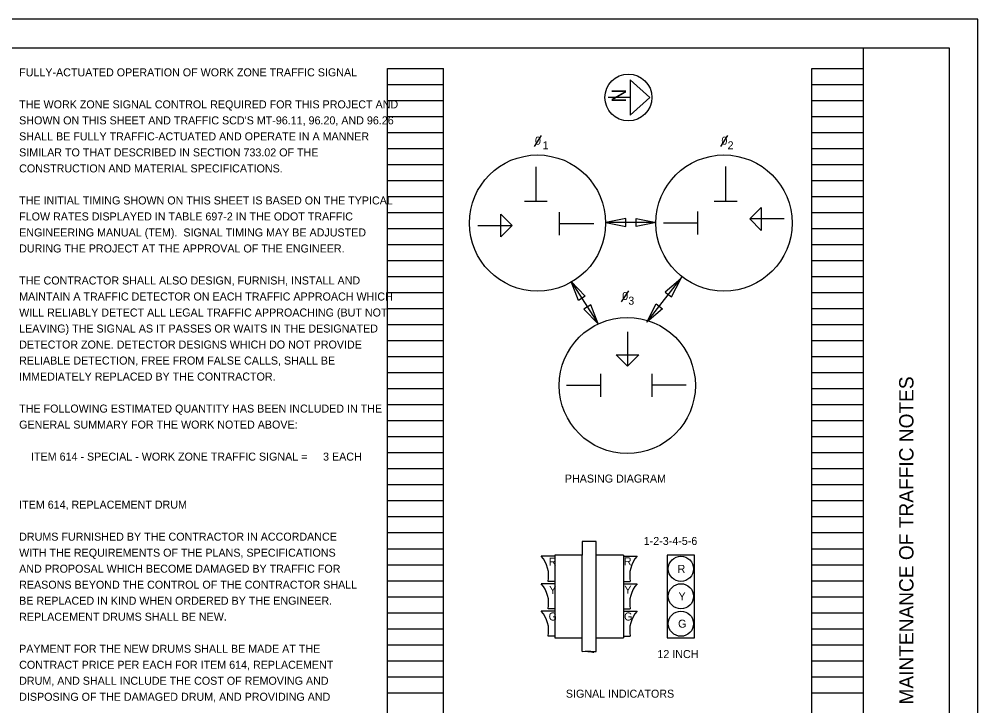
# Model space of a CAD drawing. Extents: x 0 to 34, y 0 to 22.
# Drawn here: x 17.24 to 34, y 9.99 to 22 of the extents above; entities that cross this region are included whole.
import ezdxf

# ---------------------------------------------------------------- set-up
doc = ezdxf.new("R2010")
doc.units = 0
for name, color, linetype in [('Default', 7, 'Continuous'), ('SG_P_Heads', 7, 'Continuous'), ('SH_Border', 7, 'Continuous'), ('SH_Cut_Line', 7, 'Continuous'), ('SH_Data', 7, 'Continuous'), ('SH_Masking', 7, 'Continuous'), ('SH_Text', 7, 'Continuous'), ('TX_P_1', 7, 'Continuous')]:
    doc.layers.add(name, color=color, linetype=linetype)

msp = doc.modelspace()

# ---------------------------------------------------------------- linework, layer by layer
at = {"layer": 'Default'}
for p, q in [((27.325, 12.863), (27.085, 12.863)), ((27.085, 12.863), (27.085, 12.624)), ((27.325, 10.942), (27.325, 12.863)), ((26.607, 12.607), (26.367, 12.607)), ((27.085, 12.624), (26.607, 12.624)), ((26.607, 12.624), (26.607, 11.182)), ((27.085, 11.182), (27.085, 12.624)), ((27.803, 12.624), (27.325, 12.624)), ((27.803, 12.624), (27.803, 11.182)), ((27.803, 12.607), (28.043, 12.607)), ((29.049, 12.624), (28.571, 12.624)), ((28.571, 12.624), (28.571, 11.182)), ((29.049, 11.182), (29.049, 12.624)), ((26.607, 12.127), (26.367, 12.127)), ((26.607, 12.167), (26.487, 12.167)), ((27.803, 12.167), (27.923, 12.167)), ((27.803, 12.127), (28.043, 12.127)), ((26.607, 11.648), (26.367, 11.648)), ((26.607, 11.687), (26.487, 11.687)), ((27.803, 11.687), (27.923, 11.687)), ((27.803, 11.648), (28.043, 11.648)), ((26.607, 11.208), (26.487, 11.208)), ((26.607, 11.182), (27.085, 11.182)), ((27.085, 10.942), (27.085, 11.182)), ((27.325, 11.182), (27.803, 11.182)), ((27.803, 11.208), (27.923, 11.208)), ((28.571, 11.182), (29.049, 11.182))]:
    msp.add_line(p, q, dxfattribs=at)
for centre in [(28.809, 12.387), (28.809, 11.907), (28.809, 11.428)]:
    msp.add_circle(centre, 0.22, dxfattribs=at)
for centre, start, end in [((25.992, 12.268), 348.4413, 42.0232), ((28.418, 12.268), 137.9768, 191.5587), ((25.992, 11.788), 348.4413, 42.0232), ((28.418, 11.788), 137.9768, 191.5587), ((25.992, 11.309), 348.4413, 42.0232), ((28.418, 11.309), 137.9768, 191.5587)]:
    msp.add_arc(centre, 0.505, start, end, dxfattribs=at)
msp.add_open_spline([(27.085, 10.942), (27.152, 10.961), (27.266, 10.92), (27.325, 10.942), (27.085, 10.942), (27.325, 10.942)], degree=3, dxfattribs=at)
at = {"layer": 'SG_P_Heads'}
for p, q in [((26.274, 19.417), (26.274, 18.816)), ((29.591, 19.421), (29.591, 18.82)), ((26.073, 18.816), (26.473, 18.816)), ((29.391, 18.82), (29.791, 18.82)), ((26.683, 18.624), (26.683, 18.224)), ((29.103, 18.237), (29.103, 18.637)), ((28.502, 18.437), (29.103, 18.437)), ((30.614, 18.507), (30.013, 18.507)), ((25.26, 18.392), (25.861, 18.392)), ((27.284, 18.423), (26.683, 18.423)), ((27.876, 16.53), (27.876, 15.929)), ((27.412, 15.397), (27.412, 15.797)), ((28.303, 15.797), (28.303, 15.397)), ((26.811, 15.597), (27.412, 15.597)), ((28.903, 15.597), (28.303, 15.597))]:
    msp.add_line(p, q, dxfattribs=at)
for points in [[(30.213, 18.307), (30.013, 18.507), (30.213, 18.707)], [(25.661, 18.592), (25.861, 18.392), (25.661, 18.192)], [(27.845, 18.513), (27.495, 18.443), (27.845, 18.373)], [(28.029, 18.513), (28.379, 18.443), (28.029, 18.373)], [(28.647, 17.142), (28.806, 17.461), (28.536, 17.228)], [(27.019, 17.078), (26.892, 17.411), (27.138, 17.153)], [(27.114, 16.928), (27.36, 16.67), (27.232, 17.003)], [(28.486, 16.935), (28.216, 16.701), (28.375, 17.02)], [(28.076, 16.129), (27.876, 15.929), (27.676, 16.129)]]:
    msp.add_lwpolyline(points, close=True, dxfattribs=at)
at = {"layer": 'SH_Border'}
msp.add_line((32, 0.5), (32, 21.5), dxfattribs=at)
msp.add_lwpolyline([(1.5, 21.5), (33.5, 21.5), (33.5, 0.5), (1.5, 0.5)], close=True, dxfattribs=at)
at = {"layer": 'SH_Cut_Line'}
msp.add_lwpolyline([(0, 0), (34, 0), (34, 22), (0, 22)], close=True, dxfattribs=at)
at = {"layer": 'SH_Data'}
for p, q in [((23.68, 0.98), (23.68, 21.14)), ((23.68, 21.14), (24.66, 21.14)), ((24.66, 0.98), (24.66, 21.14)), ((31.1, 0.98), (31.1, 21.14)), ((31.1, 21.14), (32, 21.14)), ((32, 0.98), (32, 21.14)), ((23.68, 20.86), (24.66, 20.86)), ((31.1, 20.86), (32, 20.86)), ((23.68, 20.58), (24.66, 20.58)), ((31.1, 20.58), (32, 20.58)), ((23.68, 20.3), (24.66, 20.3)), ((31.1, 20.3), (32, 20.3)), ((23.68, 20.02), (24.66, 20.02)), ((26.367, 19.968), (26.242, 19.775)), ((29.626, 19.968), (29.501, 19.775)), ((31.1, 20.02), (32, 20.02)), ((23.68, 19.74), (24.66, 19.74)), ((31.1, 19.74), (32, 19.74)), ((23.68, 19.46), (24.66, 19.46)), ((31.1, 19.46), (32, 19.46)), ((23.68, 19.18), (24.66, 19.18)), ((31.1, 19.18), (32, 19.18)), ((23.68, 18.9), (24.66, 18.9)), ((31.1, 18.9), (32, 18.9)), ((23.68, 18.62), (24.66, 18.62)), ((31.1, 18.62), (32, 18.62)), ((28.369, 18.443), (27.495, 18.443)), ((23.68, 18.34), (24.66, 18.34)), ((31.1, 18.34), (32, 18.34)), ((23.68, 18.06), (24.66, 18.06)), ((31.1, 18.06), (32, 18.06)), ((23.68, 17.78), (24.66, 17.78)), ((31.1, 17.78), (32, 17.78)), ((23.68, 17.5), (24.66, 17.5)), ((28.236, 16.728), (28.831, 17.494)), ((31.1, 17.5), (32, 17.5)), ((26.897, 17.402), (27.36, 16.67)), ((23.68, 17.22), (24.66, 17.22)), ((27.89, 17.251), (27.765, 17.059)), ((31.1, 17.22), (32, 17.22)), ((23.68, 16.94), (24.66, 16.94)), ((31.1, 16.94), (32, 16.94)), ((23.68, 16.66), (24.66, 16.66)), ((31.1, 16.66), (32, 16.66)), ((23.68, 16.38), (24.66, 16.38)), ((31.1, 16.38), (32, 16.38)), ((23.68, 16.1), (24.66, 16.1)), ((31.1, 16.1), (32, 16.1)), ((23.68, 15.82), (24.66, 15.82)), ((31.1, 15.82), (32, 15.82)), ((23.68, 15.54), (24.66, 15.54)), ((31.1, 15.54), (32, 15.54)), ((23.68, 15.26), (24.66, 15.26)), ((31.1, 15.26), (32, 15.26)), ((23.68, 14.98), (24.66, 14.98)), ((31.1, 14.98), (32, 14.98)), ((23.68, 14.7), (24.66, 14.7)), ((31.1, 14.7), (32, 14.7)), ((23.68, 14.42), (24.66, 14.42)), ((31.1, 14.42), (32, 14.42)), ((23.68, 14.14), (24.66, 14.14)), ((31.1, 14.14), (32, 14.14)), ((23.68, 13.86), (24.66, 13.86)), ((31.1, 13.86), (32, 13.86)), ((23.68, 13.58), (24.66, 13.58)), ((31.1, 13.58), (32, 13.58)), ((23.68, 13.3), (24.66, 13.3)), ((31.1, 13.3), (32, 13.3)), ((23.68, 13.02), (24.66, 13.02)), ((31.1, 13.02), (32, 13.02)), ((23.68, 12.74), (24.66, 12.74)), ((31.1, 12.74), (32, 12.74)), ((23.68, 12.46), (24.66, 12.46)), ((31.1, 12.46), (32, 12.46)), ((23.68, 12.18), (24.66, 12.18)), ((31.1, 12.18), (32, 12.18)), ((23.68, 11.9), (24.66, 11.9)), ((31.1, 11.9), (32, 11.9)), ((23.68, 11.62), (24.66, 11.62)), ((31.1, 11.62), (32, 11.62)), ((23.68, 11.34), (24.66, 11.34)), ((31.1, 11.34), (32, 11.34)), ((23.68, 11.06), (24.66, 11.06)), ((31.1, 11.06), (32, 11.06)), ((23.68, 10.78), (24.66, 10.78)), ((31.1, 10.78), (32, 10.78)), ((23.68, 10.5), (24.66, 10.5)), ((31.1, 10.5), (32, 10.5)), ((23.68, 10.22), (24.66, 10.22)), ((31.1, 10.22), (32, 10.22))]:
    msp.add_line(p, q, dxfattribs=at)
for centre in [(26.302, 18.434), (29.562, 18.434), (27.871, 15.594)]:
    msp.add_circle(centre, 1.191, dxfattribs=at)
at = {"layer": 'SH_Masking'}
msp.add_circle((27.891, 20.631), 0.41, dxfattribs=at)
at = {"layer": 'SH_Text'}
for p, q in [((28.265, 20.631), (27.924, 20.939)), ((27.924, 20.939), (27.924, 20.324)), ((27.924, 20.631), (27.537, 20.631)), ((27.924, 20.324), (28.265, 20.631))]:
    msp.add_line(p, q, dxfattribs=at)
msp.add_circle((27.891, 20.631), 0.41, dxfattribs=at)

# ---------------------------------------------------------------- texts
at = {"layer": 'Default'}
for s, p in [('R', (26.499, 12.443)), ('R', (27.812, 12.448)), ('R', (28.751, 12.317)), ('Y', (26.506, 11.946)), ('Y', (27.82, 11.951)), ('Y', (28.767, 11.837)), ('G', (26.496, 11.484)), ('G', (27.815, 11.484)), ('G', (28.76, 11.358)), ('SIGNAL INDICATORS', (26.798, 10.134))]:
    msp.add_text(s, height=0.14, dxfattribs=at).set_placement(p)
at = {"layer": 'SH_Data'}
for s, p in [('0', (26.258, 19.805)), ('0', (29.517, 19.805)), ('1', (26.392, 19.724)), ('2', (29.625, 19.724)), ('0', (27.782, 17.089)), ('3', (27.889, 17.007)), ('PHASING DIAGRAM', (26.78, 13.896))]:
    msp.add_text(s, height=0.14, dxfattribs=at).set_placement(p)
msp.add_text('MAINTENANCE OF TRAFFIC NOTES', height=0.25, rotation=90, dxfattribs=at).set_placement((32.875, 10.014))
at = {"layer": 'SH_Text'}
for s, p in [('FULLY-ACTUATED OPERATION OF WORK ZONE TRAFFIC SIGNAL', (17.24, 21)), ('THE WORK ZONE SIGNAL CONTROL REQUIRED FOR THIS PROJECT AND ', (17.24, 20.44)), ("SHOWN ON THIS SHEET AND TRAFFIC SCD'S MT-96.11, 96.20, AND 96.26 ", (17.24, 20.16)), ('SHALL BE FULLY TRAFFIC-ACTUATED AND OPERATE IN A MANNER ', (17.24, 19.88)), ('SIMILAR TO THAT DESCRIBED IN SECTION 733.02 OF THE ', (17.24, 19.6)), ('CONSTRUCTION AND MATERIAL SPECIFICATIONS.', (17.24, 19.32)), ('THE INITIAL TIMING SHOWN ON THIS SHEET IS BASED ON THE TYPICAL ', (17.24, 18.76)), ('FLOW RATES DISPLAYED IN TABLE 697-2 IN THE ODOT TRAFFIC ', (17.24, 18.48)), ('ENGINEERING MANUAL (TEM).  SIGNAL TIMING MAY BE ADJUSTED ', (17.24, 18.2)), ('DURING THE PROJECT AT THE APPROVAL OF THE ENGINEER.', (17.24, 17.92)), ('THE CONTRACTOR SHALL ALSO DESIGN, FURNISH, INSTALL AND ', (17.24, 17.36)), ('MAINTAIN A TRAFFIC DETECTOR ON EACH TRAFFIC APPROACH WHICH ', (17.24, 17.08)), ('WILL RELIABLY DETECT ALL LEGAL TRAFFIC APPROACHING (BUT NOT ', (17.24, 16.8)), ('LEAVING) THE SIGNAL AS IT PASSES OR WAITS IN THE DESIGNATED ', (17.24, 16.52)), ('DETECTOR ZONE. DETECTOR DESIGNS WHICH DO NOT PROVIDE ', (17.24, 16.24)), ('RELIABLE DETECTION, FREE FROM FALSE CALLS, SHALL BE ', (17.24, 15.96)), ('IMMEDIATELY REPLACED BY THE CONTRACTOR.', (17.24, 15.68)), ('THE FOLLOWING ESTIMATED QUANTITY HAS BEEN INCLUDED IN THE ', (17.24, 15.12)), ('GENERAL SUMMARY FOR THE WORK NOTED ABOVE:', (17.24, 14.84)), ('    ITEM 614 - SPECIAL - WORK ZONE TRAFFIC SIGNAL = ', (17.24, 14.28)), ('3 EACH', (22.553, 14.28)), ('ITEM 614, REPLACEMENT DRUM', (17.24, 13.44)), ('DRUMS FURNISHED BY THE CONTRACTOR IN ACCORDANCE', (17.24, 12.88)), ('WITH THE REQUIREMENTS OF THE PLANS, SPECIFICATIONS', (17.24, 12.6)), ('AND PROPOSAL WHICH BECOME DAMAGED BY TRAFFIC FOR', (17.24, 12.32)), ('REASONS BEYOND THE CONTROL OF THE CONTRACTOR SHALL', (17.24, 12.04)), ('BE REPLACED IN KIND WHEN ORDERED BY THE ENGINEER.', (17.24, 11.76)), ('REPLACEMENT DRUMS SHALL BE NEW.', (17.24, 11.48)), ('PAYMENT FOR THE NEW DRUMS SHALL BE MADE AT THE', (17.24, 10.92)), ('CONTRACT PRICE PER EACH FOR ITEM 614, REPLACEMENT', (17.24, 10.64)), ('DRUM, AND SHALL INCLUDE THE COST OF REMOVING AND', (17.24, 10.36)), ('DISPOSING OF THE DAMAGED DRUM, AND PROVIDING AND', (17.24, 10.08))]:
    msp.add_text(s, height=0.14, dxfattribs=at).set_placement(p)
msp.add_text('N', height=0.25, rotation=270, dxfattribs=at).set_placement((27.6, 20.783))
at = {"layer": 'TX_P_1'}
for s, p in [('1-2-3-4-5-6', (28.159, 12.805)), ('12 INCH', (28.398, 10.827))]:
    msp.add_text(s, height=0.14, dxfattribs=at).set_placement(p)

doc.saveas('drawing.dxf')
